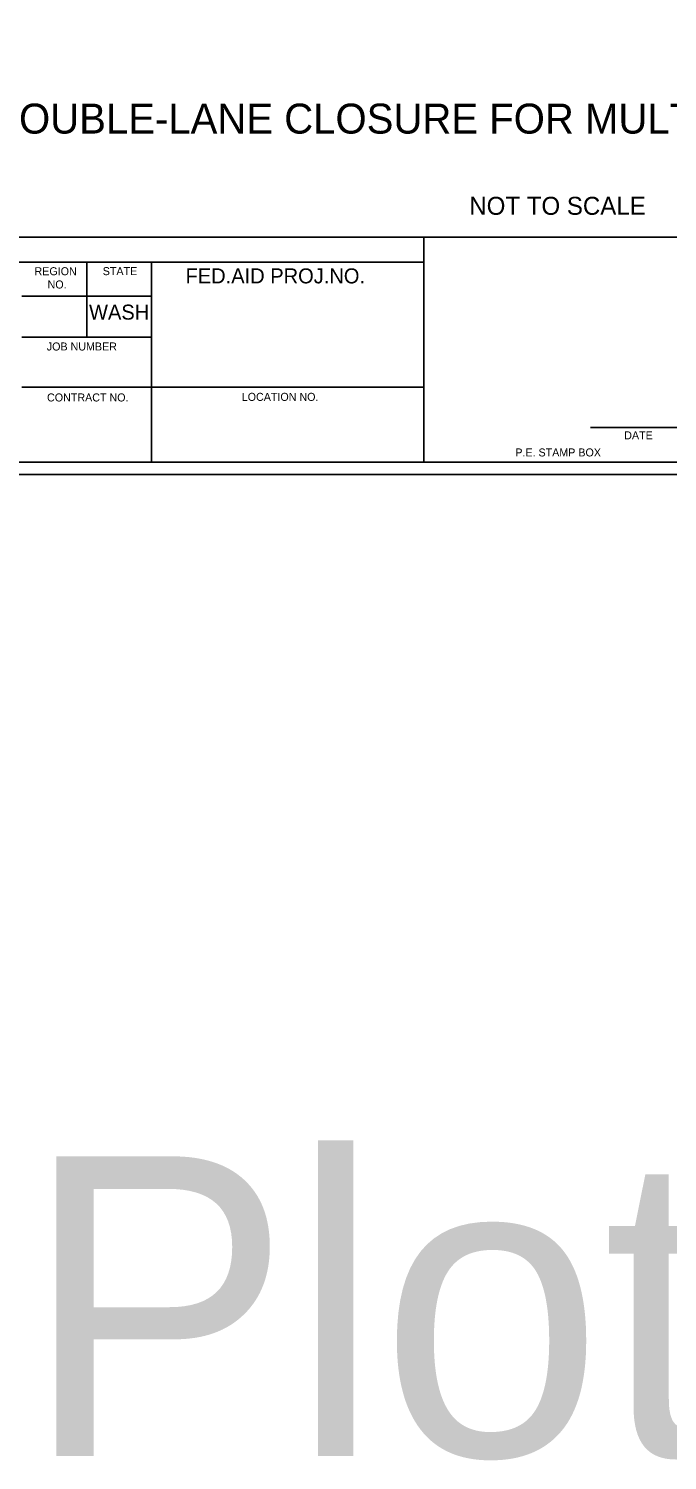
# Model space of a CAD drawing. Extents: x 99988 to 100172, y 99995 to 100047.
# Drawn here: x 100005.48 to 100008.68, y 99995.01 to 100002.17 of the extents above; entities that cross this region are included whole.
import ezdxf

# ---------------------------------------------------------------- set-up
doc = ezdxf.new("R2010")
doc.units = 0
for name, color, linetype in [('SH_DE_DetailHeading1Text', 7, 'Continuous'), ('SH_DE_DetailHeading3Text', 7, 'Continuous'), ('SH_GI_PlotLimits', 7, 'Continuous'), ('SH_GI_SheetBorder', 7, 'Continuous'), ('SH_GI_SheetLocationText', 7, 'Continuous'), ('SH_GI_SheetTextInCells', 7, 'Continuous')]:
    doc.layers.add(name, color=color, linetype=linetype)

msp = doc.modelspace()

# ---------------------------------------------------------------- linework, layer by layer
at = {"layer": 'SH_GI_PlotLimits'}
msp.add_lwpolyline([(99999.3125, 99999.9375), (100015.8125, 99999.9375), (100015.8125, 100010.4375), (99999.3125, 100010.4375)], close=True, dxfattribs=at)
at = {"layer": 'SH_GI_SheetBorder'}
for p, q in [((100000, 100001.1259), (100015.75, 100001.1259)), ((100007.4566, 100000), (100007.4566, 100001.1259)), ((100000, 100001.0008), (100007.4566, 100001.0008)), ((100005.7719, 100000.6255), (100005.7719, 100001.0008)), ((100006.0956, 100000), (100006.0956, 100001.0008)), ((100006.0958, 100000.831), (100005.4466, 100000.831)), ((100006.0958, 100000.6255), (100005.4466, 100000.6255)), ((100007.4566, 100000.3753), (100005.4466, 100000.3753)), ((100008.2903, 100000.1733), (100008.802, 100000.1733)), ((100000, 100000), (100015.75, 100000))]:
    msp.add_line(p, q, dxfattribs=at)

# ---------------------------------------------------------------- texts
at = {"layer": 'SH_DE_DetailHeading1Text'}
msp.add_text('DOUBLE-LANE CLOSURE FOR MULTI-LANE ROADWAYS', height=0.15, dxfattribs=at).set_placement((100005.2875, 100001.644))
at = {"layer": 'SH_DE_DetailHeading3Text'}
msp.add_text('NOT TO SCALE', height=0.09, dxfattribs=at).set_placement((100007.6847, 100001.2376))
at = {"layer": 'SH_GI_SheetLocationText'}
msp.add_text('Plot 1', height=1.5, dxfattribs=at).set_placement((100005.4547, 99995.0267))
at = {"layer": 'SH_GI_SheetTextInCells'}
for s, height, p in [('REGION', 0.04003, (100005.5099, 100000.9352)), ('STATE', 0.04003, (100005.8511, 100000.9357)), ('FED.AID PROJ.NO.', 0.07506, (100006.2652, 100000.8945)), ('NO.', 0.04003, (100005.5752, 100000.869)), ('WASH', 0.07506, (100005.7826, 100000.7131)), ('JOB NUMBER', 0.04003, (100005.5712, 100000.5587)), ('CONTRACT NO.', 0.040032, (100005.5725, 100000.3037)), ('LOCATION NO.', 0.040032, (100006.5465, 100000.3067)), ('DATE', 0.04003, (100008.4597, 100000.1141)), ('P.E. STAMP BOX', 0.040032, (100007.915, 100000.0286))]:
    msp.add_text(s, height=height, dxfattribs=at).set_placement(p)

doc.saveas('drawing.dxf')
